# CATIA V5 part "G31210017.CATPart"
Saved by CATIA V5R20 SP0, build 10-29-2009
Part number: G31210017
Revision: 25
Definition: design
Nomenclature: G31210017
Source: made
Description: NOT SPECIFIED
Bounding box of the stored display mesh (mm): x -5 to 17, y -8 to 8, z -8 to 8
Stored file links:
  C:\Users\Raffaele\Desktop\3D X SITO CF\BOLEX\23-BUSH REF 312\G31210017.CATPart

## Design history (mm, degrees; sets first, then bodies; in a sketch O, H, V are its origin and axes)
Body1 "MANIFOLD_SOLID_BREP #3459" (main body)
  Solid1: solid without history
Body2 "MANIFOLD_SOLID_BREP #3602"
  Solid2: solid without history
Body3 "MANIFOLD_SOLID_BREP #3745"
  Solid3: solid without history
Body4 "MANIFOLD_SOLID_BREP #3888"
  Solid4: solid without history
Body5 "MANIFOLD_SOLID_BREP #4031"
  Solid5: solid without history
Body6 "MANIFOLD_SOLID_BREP #4174"
  Solid6: solid without history
Body7 "MANIFOLD_SOLID_BREP #4317"
  Solid7: solid without history
Body8 "MANIFOLD_SOLID_BREP #4462"
  Solid8: solid without history
Body9 "MANIFOLD_SOLID_BREP #4607"
  Solid9: solid without history
Body10 "MANIFOLD_SOLID_BREP #4752"
  Solid10: solid without history
Body11 "MANIFOLD_SOLID_BREP #4897"
  Solid11: solid without history
Body12 "MANIFOLD_SOLID_BREP #5040"
  Solid12: solid without history
Body13 "MANIFOLD_SOLID_BREP #5183"
  Solid13: solid without history
Body14 "MANIFOLD_SOLID_BREP #5328"
  Solid14: solid without history
Body15 "MANIFOLD_SOLID_BREP #5473"
  Solid15: solid without history
Body16 "MANIFOLD_SOLID_BREP #5618"
  Solid16: solid without history
Body17 "MANIFOLD_SOLID_BREP #5763"
  Solid17: solid without history
Body18 "MANIFOLD_SOLID_BREP #5908"
  Solid18: solid without history
Body19 "MANIFOLD_SOLID_BREP #6051"
  Solid19: solid without history
Body20 "MANIFOLD_SOLID_BREP #6194"
  Solid20: solid without history
Body21 "MANIFOLD_SOLID_BREP #6339"
  Solid21: solid without history
Body22 "MANIFOLD_SOLID_BREP #6482"
  Solid22: solid without history
Body23 "MANIFOLD_SOLID_BREP #6627"
  Solid23: solid without history
Body24 "MANIFOLD_SOLID_BREP #6772"
  Solid24: solid without history
Body25 "MANIFOLD_SOLID_BREP #6915"
  Solid25: solid without history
